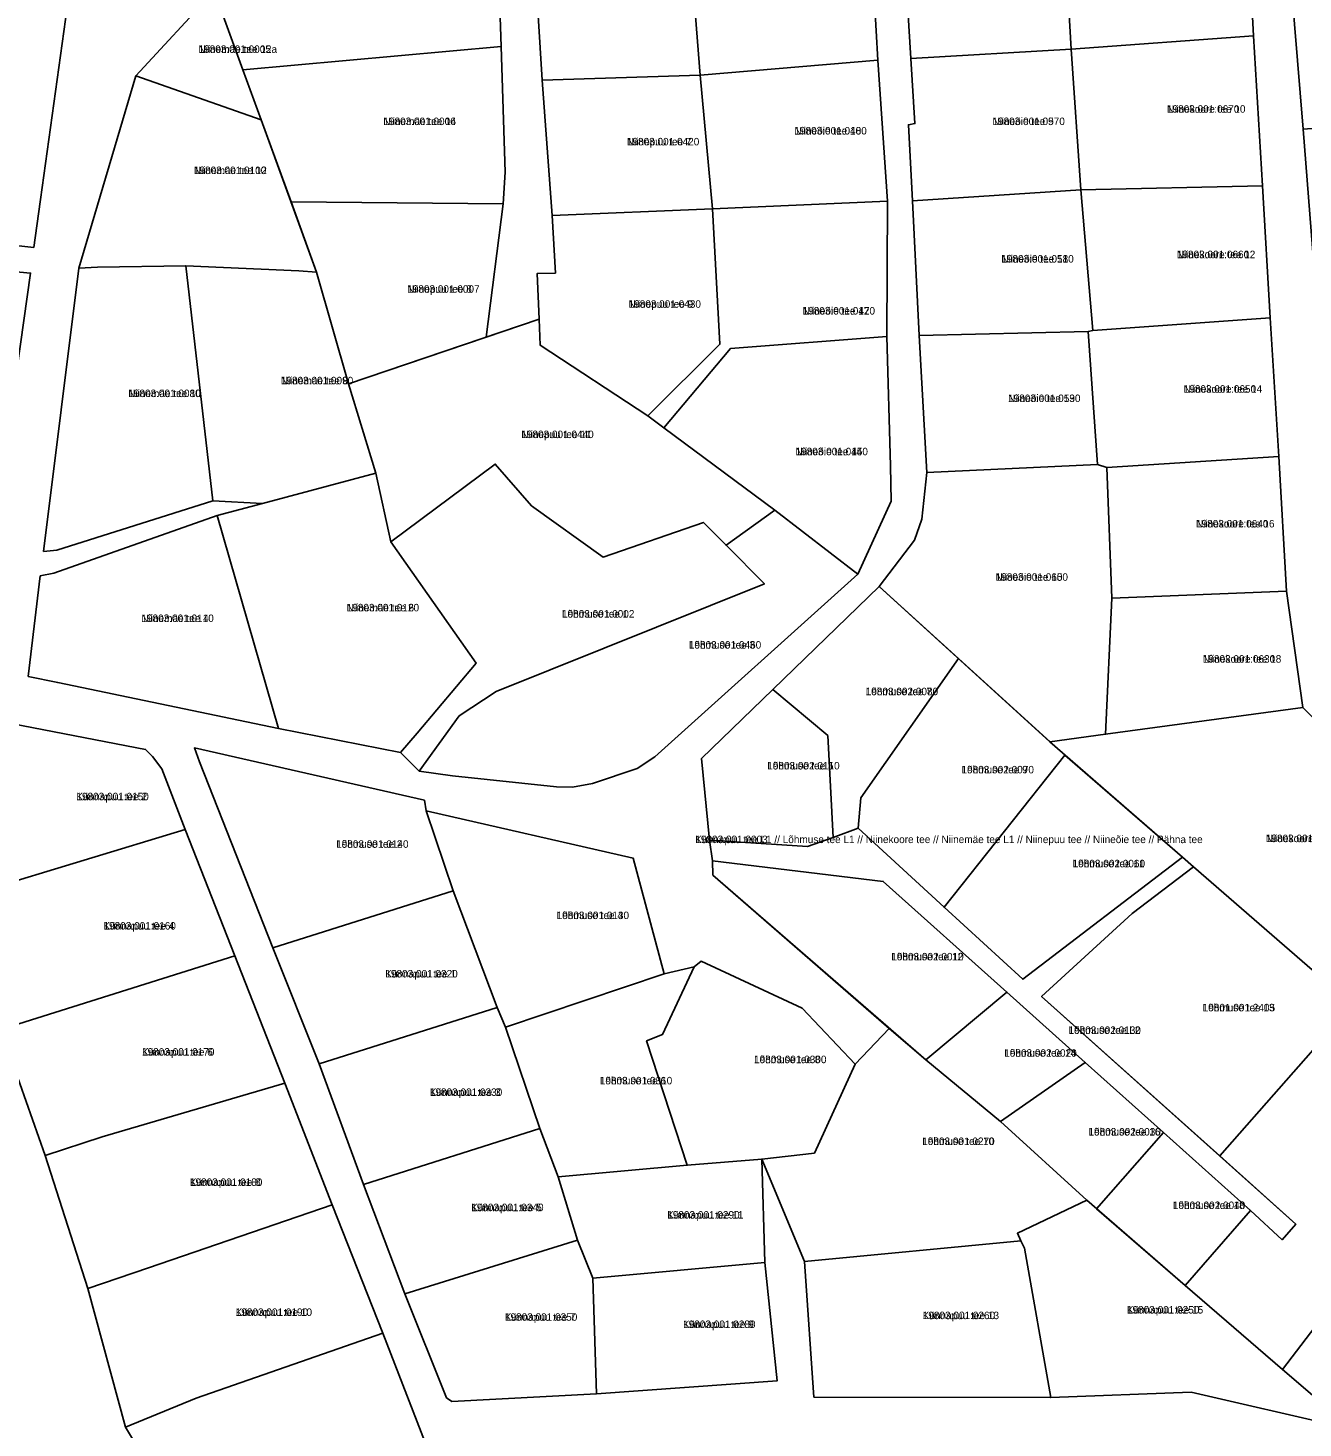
# Model space of a CAD drawing. Extents: x 516875 to 535633, y 6574491 to 6593094.
# Drawn here: x 521689.3 to 521944.6, y 6591928 to 6592208.3 of the extents above; entities that cross this region are included whole.
import ezdxf

# ---------------------------------------------------------------- set-up
doc = ezdxf.new("R2010")
doc.units = 0
for name, color, linetype in [('L_AADRESS', 7, 'Continuous'), ('PIIR', 7, 'Continuous'), ('TUNNUS', 7, 'Continuous')]:
    doc.layers.add(name, color=color, linetype=linetype)

msp = doc.modelspace()

# ---------------------------------------------------------------- linework, layer by layer
at = {"layer": 'PIIR'}
for points in [[(521940.61, 6592236.6), (521942.91, 6592237.96), (521975.67, 6592236.53), (521975.53, 6592224.7), (521977.35, 6592190.49), (521944.62, 6592187.97)], [(521866.04, 6592202.15), (521864.22, 6592232.76), (521866.15, 6592233.77), (521896.35, 6592235.26), (521898.2, 6592203.99)], [(521896.35, 6592235.26), (521931.96, 6592237.36), (521933.17, 6592237.01), (521934.78, 6592232.86), (521933.37, 6592230.79), (521934.69, 6592206.69), (521898.2, 6592203.99)], [(521821.3, 6592231.76), (521854.33, 6592233.21), (521857.76, 6592231.23), (521859.45, 6592201.8), (521823.92, 6592198.81)], [(521726.6, 6592215.69), (521747.49, 6592217.82), (521747.49, 6592223.01), (521780.82, 6592229.71), (521783.32, 6592226.15), (521784.02, 6592204.57), (521732.36, 6592199.91)], [(521792.29, 6592197.79), (521790.25, 6592230.25), (521821.3, 6592231.76), (521823.92, 6592198.81)], [(521656.25, 6592216.57), (521689.09, 6592218.47), (521694.09, 6592214.92), (521697.14, 6592212.36), (521690.48, 6592164.34), (521673.6, 6592166.16), (521668.99, 6592168.86), (521653.45, 6592196.6), (521652.38, 6592216.11)], [(521726.6, 6592215.69), (521732.36, 6592199.91), (521736.02, 6592189.86), (521710.89, 6592198.65)], [(521732.36, 6592199.91), (521784.02, 6592204.57), (521784.82, 6592179.41), (521784.43, 6592173.07), (521741.99, 6592173.48), (521736.02, 6592189.86)], [(521866.43, 6592173.64), (521865.57, 6592188.87), (521866.87, 6592189.13), (521866.04, 6592202.15), (521898.2, 6592203.99), (521900.11, 6592175.88)], [(521898.2, 6592203.99), (521934.69, 6592206.69), (521936.49, 6592176.65), (521900.11, 6592175.88)], [(521823.92, 6592198.81), (521859.45, 6592201.8), (521861.43, 6592173.58), (521826.35, 6592172.06)], [(521703.22, 6592160.38), (521699.53, 6592160.2), (521710.89, 6592198.65), (521736.02, 6592189.86), (521747.11, 6592159.38), (521743.56, 6592159.61), (521720.9, 6592160.66)], [(521794.26, 6592170.69), (521792.29, 6592197.79), (521823.92, 6592198.81), (521826.35, 6592172.06)], [(521936.49, 6592176.65), (521938.04, 6592150.21), (521902.51, 6592147.69), (521900.11, 6592175.88)], [(521741.99, 6592173.48), (521784.43, 6592173.07), (521781.06, 6592146.37), (521753.48, 6592137.02), (521747.11, 6592159.38)], [(521816.6, 6592128.17), (521813.39, 6592130.61), (521827.85, 6592144.94), (521826.35, 6592172.06), (521861.43, 6592173.58), (521861.25, 6592146.5), (521829.94, 6592144.06)], [(521902.51, 6592147.69), (521901.57, 6592147.48), (521867.71, 6592146.69), (521866.43, 6592173.64), (521900.11, 6592175.88)], [(521813.39, 6592130.61), (521791.89, 6592144.75), (521791.65, 6592149.96), (521791.25, 6592159.09), (521794.91, 6592159.19), (521794.26, 6592170.69), (521826.35, 6592172.06), (521827.85, 6592144.94)], [(521672.05, 6592158.02), (521673.1, 6592161.92), (521678.47, 6592160.23), (521689.85, 6592159.2), (521685.1, 6592125.56), (521659.5, 6592116.72), (521657.72, 6592121.29), (521647.38, 6592146.56)], [(521703.22, 6592160.38), (521720.9, 6592160.66), (521726.31, 6592113.6), (521695.07, 6592103.72), (521692.46, 6592103.46), (521699.53, 6592160.2)], [(521743.56, 6592159.61), (521747.11, 6592159.38), (521753.48, 6592137.02), (521758.95, 6592119.16), (521736.29, 6592113.08), (521726.31, 6592113.6), (521720.9, 6592160.66)], [(521816.6, 6592128.17), (521838.83, 6592111.75), (521829.09, 6592104.69), (521824.53, 6592109.28), (521804.44, 6592102.33), (521790.11, 6592112.61), (521782.88, 6592120.96), (521761.99, 6592105.36), (521758.95, 6592119.16), (521753.48, 6592137.02), (521791.65, 6592149.96), (521791.89, 6592144.75), (521813.39, 6592130.61)], [(521938.04, 6592150.21), (521939.71, 6592122.44), (521905.29, 6592120.27), (521903.47, 6592120.89), (521901.57, 6592147.48), (521902.51, 6592147.69)], [(521829.94, 6592144.06), (521861.25, 6592146.5), (521862.03, 6592120.62), (521862.14, 6592113.49), (521855.45, 6592098.92), (521838.83, 6592111.75), (521816.6, 6592128.17)], [(521869.3, 6592119.26), (521867.71, 6592146.69), (521901.57, 6592147.48), (521903.47, 6592120.89)], [(521761.99, 6592105.36), (521782.88, 6592120.96), (521790.11, 6592112.61), (521804.44, 6592102.33), (521824.53, 6592109.28), (521829.09, 6592104.69), (521836.74, 6592096.99), (521783.02, 6592075.42), (521775.64, 6592070.53), (521767.64, 6592059.46), (521763.9, 6592063.19), (521767.25, 6592067.07), (521779.02, 6592081.06)], [(521905.29, 6592120.27), (521906.34, 6592094.08), (521905.05, 6592066.86), (521893.89, 6592065.37), (521859.72, 6592096.42), (521866.82, 6592105.69), (521868.27, 6592109.93), (521869.3, 6592119.26), (521903.47, 6592120.89)], [(521905.29, 6592120.27), (521939.71, 6592122.44), (521941.31, 6592095.51), (521906.34, 6592094.08)], [(521736.29, 6592113.08), (521758.95, 6592119.16), (521761.99, 6592105.36), (521779.02, 6592081.06), (521767.25, 6592067.07), (521763.9, 6592063.19), (521739.5, 6592068.02), (521727.21, 6592110.65)], [(521775.64, 6592070.53), (521783.02, 6592075.42), (521836.74, 6592096.99), (521829.09, 6592104.69), (521838.83, 6592111.75), (521855.45, 6592098.92), (521814.8, 6592062.36), (521811.26, 6592059.99), (521802.31, 6592056.97), (521798.32, 6592056.25), (521795.11, 6592056.31), (521774.3, 6592058.53), (521767.64, 6592059.46)], [(521694.48, 6592099.11), (521727.21, 6592110.65), (521739.5, 6592068.02), (521695.28, 6592077.2), (521689.37, 6592078.43), (521691.79, 6592098.56)], [(521859.72, 6592096.42), (521875.6, 6592081.99), (521856.03, 6592054.12), (521855.54, 6592048.08), (521850.49, 6592046.18), (521849.47, 6592066.6), (521838.45, 6592075.83)], [(521906.34, 6592094.08), (521941.31, 6592095.51), (521944.54, 6592072.18), (521905.05, 6592066.86)], [(521875.6, 6592081.99), (521896.88, 6592062.65), (521872.73, 6592032.22), (521855.54, 6592048.08), (521856.03, 6592054.12)], [(521849.47, 6592066.6), (521850.49, 6592046.18), (521845.41, 6592044.35), (521825.78, 6592045.66), (521824.14, 6592062), (521838.45, 6592075.83)], [(521678.44, 6592044.05), (521681.99, 6592047.8), (521671.75, 6592071.76), (521712.85, 6592063.82), (521714.26, 6592062.42), (521716.13, 6592059.96), (521720.76, 6592047.76), (521680.27, 6592035.51)], [(521905.05, 6592066.86), (521944.54, 6592072.18), (521949.8, 6592066.84), (521956.14, 6592049.35), (521957.62, 6592043.92), (521957.58, 6592033.05), (521958.82, 6592029.22), (521947.95, 6592018.33), (521922.65, 6592040.34), (521920.48, 6592042.23), (521893.89, 6592065.37)], [(521723.65, 6592061.35), (521722.63, 6592064.11), (521768.68, 6592053.65), (521769.06, 6592051.5), (521774.45, 6592035.49), (521738.37, 6592024.12)], [(521896.88, 6592062.65), (521920.48, 6592042.23), (521888.46, 6592017.79), (521872.73, 6592032.22)], [(521783.26, 6592012.18), (521774.45, 6592035.49), (521769.06, 6592051.5), (521810.5, 6592042.04), (521816.66, 6592018.86), (521784.91, 6592008.2)], [(521680.19, 6592018.27), (521680.21, 6592022.8), (521680.27, 6592035.51), (521720.76, 6592047.76), (521730.7, 6592022.5), (521683.89, 6592007.74)], [(521845.41, 6592044.35), (521850.49, 6592046.18), (521855.54, 6592048.08), (521872.73, 6592032.22), (521888.46, 6592017.79), (521920.48, 6592042.23), (521922.65, 6592040.34), (521910.39, 6592030.94), (521892.26, 6592014.38), (521943.12, 6591968.75), (521940.4, 6591965.65), (521934.07, 6591971.5), (521916.66, 6591987.12), (521900.98, 6592001.16), (521885.29, 6592015.24), (521860.55, 6592037.38), (521826.37, 6592041.52), (521825.78, 6592045.66)], [(521860.55, 6592037.38), (521885.29, 6592015.24), (521869.05, 6592001.64), (521826.42, 6592038.67), (521826.37, 6592041.52)], [(521954.46, 6592012.61), (521927.9, 6591982.42), (521892.26, 6592014.38), (521910.39, 6592030.94), (521922.65, 6592040.34), (521947.95, 6592018.33)], [(521738.37, 6592024.12), (521774.45, 6592035.49), (521783.26, 6592012.18), (521747.6, 6592000.84)], [(521639.58, 6592001.15), (521639.64, 6592001.17), (521680.21, 6592022.8), (521680.19, 6592018.27), (521683.89, 6592007.74), (521692.77, 6591982.51), (521701.33, 6591955.9), (521708.82, 6591928.16), (521722.97, 6591904.65), (521731.68, 6591881.94), (521745.45, 6591847.74), (521757.09, 6591827.34), (521755.99, 6591825.24), (521698.88, 6591854.65), (521689.15, 6591863.66), (521680.26, 6591879.32), (521637.95, 6592000.51)], [(521692.77, 6591982.51), (521683.89, 6592007.74), (521730.7, 6592022.5), (521740.74, 6591996.97), (521704.14, 6591986.25)], [(521791.8, 6591987.92), (521784.91, 6592008.2), (521816.66, 6592018.86), (521822.69, 6592020.29), (521816.37, 6592006.72), (521813.18, 6592005.47), (521821.32, 6591980.57), (521795.44, 6591978.22)], [(521813.18, 6592005.47), (521816.37, 6592006.72), (521822.69, 6592020.29), (521824.09, 6592021.43), (521844.31, 6592012.02), (521854.94, 6592000.77), (521846.76, 6591983.01), (521836.21, 6591981.79), (521821.32, 6591980.57)], [(521885.29, 6592015.24), (521900.98, 6592001.16), (521884.04, 6591989.34), (521869.05, 6592001.64)], [(521747.6, 6592000.84), (521783.26, 6592012.18), (521784.91, 6592008.2), (521791.8, 6591987.92), (521756.51, 6591976.72)], [(521943.12, 6591968.75), (521927.9, 6591982.42), (521954.46, 6592012.61), (521968.51, 6592000.46), (521969.89, 6591999.23), (521979.93, 6591990.62), (521961.47, 6591970.68), (521962, 6591967.92), (521940.5, 6591939.68), (521921.02, 6591956.48), (521934.07, 6591971.5), (521940.4, 6591965.65)], [(521836.21, 6591981.79), (521846.76, 6591983.01), (521854.94, 6592000.77), (521861.76, 6592007.97), (521869.05, 6592001.64), (521884.04, 6591989.34), (521901.29, 6591973.58), (521887.4, 6591966.94), (521888.12, 6591965.45), (521844.75, 6591961.27)], [(521900.98, 6592001.16), (521916.66, 6591987.12), (521903.27, 6591971.85), (521901.29, 6591973.58), (521884.04, 6591989.34)], [(521701.33, 6591955.9), (521692.77, 6591982.51), (521704.14, 6591986.25), (521740.74, 6591996.97), (521750.24, 6591972.63), (521713.44, 6591960.04)], [(521995.95, 6591976.56), (521974.79, 6591952.48), (521993.36, 6591924.57), (521990, 6591920.93), (521974.68, 6591932.42), (521954.24, 6591933.23), (521947.41, 6591933.73), (521940.5, 6591939.68), (521962, 6591967.92), (521961.47, 6591970.68), (521979.93, 6591990.62)], [(521756.51, 6591976.72), (521791.8, 6591987.92), (521795.44, 6591978.22), (521799.34, 6591965.59), (521764.77, 6591954.82)], [(521916.66, 6591987.12), (521934.07, 6591971.5), (521921.02, 6591956.48), (521903.27, 6591971.85)], [(521799.34, 6591965.59), (521795.44, 6591978.22), (521821.32, 6591980.57), (521836.21, 6591981.79), (521836.83, 6591961.12), (521802.39, 6591957.97)], [(521708.82, 6591928.16), (521701.33, 6591955.9), (521713.44, 6591960.04), (521750.24, 6591972.63), (521760.37, 6591946.92), (521723.01, 6591933.96)], [(521887.4, 6591966.94), (521901.29, 6591973.58), (521921.02, 6591956.48), (521940.5, 6591939.68), (521947.41, 6591933.73), (521954.24, 6591933.23), (521952.28, 6591928.18), (521922.16, 6591935.12), (521894.09, 6591934.06), (521888.85, 6591963.96), (521888.12, 6591965.45)], [(521773.11, 6591934.02), (521764.77, 6591954.82), (521799.34, 6591965.59), (521802.39, 6591957.97), (521803.16, 6591934.83), (521774.2, 6591933.27)], [(521844.82, 6591960.28), (521844.75, 6591961.27), (521888.12, 6591965.45), (521888.85, 6591963.96), (521894.09, 6591934.06), (521846.65, 6591934.15)], [(521802.39, 6591957.97), (521836.83, 6591961.12), (521839.32, 6591937.41), (521803.16, 6591934.83)], [(521722.97, 6591904.65), (521708.82, 6591928.16), (521723.01, 6591933.96), (521760.37, 6591946.92), (521770.46, 6591920.93), (521731.65, 6591909.09)]]:
    msp.add_lwpolyline(points, close=True, dxfattribs=at)
for points in [[(521940.61, 6592236.6), (521944.62, 6592187.97), (521946.72, 6592160.75), (521947.99, 6592133.85), (521949.86, 6592106.6), (521951.66, 6592079.69), (521954.85, 6592065.61), (521961.38, 6592049.9), (521956.14, 6592049.35), (521949.8, 6592066.84), (521944.54, 6592072.18), (521941.31, 6592095.51), (521939.71, 6592122.44), (521938.04, 6592150.21), (521936.49, 6592176.65), (521934.69, 6592206.69), (521933.37, 6592230.79)], [(521864.22, 6592232.76), (521866.04, 6592202.15), (521866.87, 6592189.13), (521865.57, 6592188.87), (521866.43, 6592173.64), (521867.71, 6592146.69), (521869.3, 6592119.26), (521868.27, 6592109.93), (521866.82, 6592105.69), (521859.72, 6592096.42), (521838.45, 6592075.83), (521824.14, 6592062), (521825.78, 6592045.66), (521826.37, 6592041.52), (521826.42, 6592038.67), (521861.76, 6592007.97), (521854.94, 6592000.77), (521844.31, 6592012.02), (521824.09, 6592021.43), (521822.69, 6592020.29), (521816.66, 6592018.86), (521810.5, 6592042.04), (521769.06, 6592051.5), (521768.68, 6592053.65), (521722.63, 6592064.11), (521723.65, 6592061.35), (521738.37, 6592024.12), (521747.6, 6592000.84), (521756.51, 6591976.72), (521764.77, 6591954.82), (521773.11, 6591934.02), (521774.2, 6591933.27), (521803.16, 6591934.83), (521839.32, 6591937.41), (521836.83, 6591961.12), (521836.21, 6591981.79), (521844.75, 6591961.27), (521844.82, 6591960.28), (521846.65, 6591934.15), (521894.09, 6591934.06), (521922.16, 6591935.12), (521952.28, 6591928.18)], [(521726.6, 6592215.69), (521710.89, 6592198.65), (521699.53, 6592160.2), (521692.46, 6592103.46), (521695.07, 6592103.72), (521726.31, 6592113.6), (521736.29, 6592113.08), (521727.21, 6592110.65), (521694.48, 6592099.11), (521691.79, 6592098.56), (521689.37, 6592078.43), (521695.28, 6592077.2), (521739.5, 6592068.02), (521763.9, 6592063.19), (521767.64, 6592059.46), (521774.3, 6592058.53), (521795.11, 6592056.31), (521798.32, 6592056.25), (521802.31, 6592056.97), (521811.26, 6592059.99), (521814.8, 6592062.36), (521855.45, 6592098.92), (521862.14, 6592113.49), (521862.03, 6592120.62), (521861.25, 6592146.5), (521861.43, 6592173.58), (521859.45, 6592201.8), (521857.76, 6592231.23)], [(521790.25, 6592230.25), (521792.29, 6592197.79), (521794.26, 6592170.69), (521794.91, 6592159.19), (521791.25, 6592159.09), (521791.65, 6592149.96), (521781.06, 6592146.37), (521784.43, 6592173.07), (521784.82, 6592179.41), (521784.02, 6592204.57), (521783.32, 6592226.15)], [(521673.6, 6592166.16), (521690.48, 6592164.34), (521697.14, 6592212.36)], [(521685.1, 6592125.56), (521689.85, 6592159.2), (521678.47, 6592160.23)], [(521770.46, 6591920.93), (521760.37, 6591946.92), (521750.24, 6591972.63), (521740.74, 6591996.97), (521730.7, 6592022.5), (521720.76, 6592047.76), (521716.13, 6592059.96), (521714.26, 6592062.42), (521712.85, 6592063.82), (521671.75, 6592071.76)]]:
    msp.add_lwpolyline(points, dxfattribs=at)

# ---------------------------------------------------------------- texts
at = {"layer": 'L_AADRESS'}
for s, p in [('Niinemäe tee 12a', (521723.46, 6592203.27)), ('Niinekoore tee 10', (521917.34, 6592191.29)), ('Niinemäe tee 14', (521760.46, 6592188.82)), ('Niineõie tee 9', (521882.4, 6592188.82)), ('Niineõie tee 10', (521842.75, 6592186.93)), ('Niinepuu tee 7', (521809.22, 6592184.75)), ('Niinemäe tee 12', (521722.53, 6592179.01)), ('Niineõie tee 11', (521884.18, 6592161.29)), ('Niinekoore tee 12', (521919.31, 6592162.17)), ('Niinepuu tee 8', (521765.23, 6592155.25)), ('Niinepuu tee 9', (521809.55, 6592152.24)), ('Niineõie tee 12', (521844.4, 6592150.88)), ('Niinemäe tee 8', (521739.93, 6592136.92)), ('Niinekoore tee 14', (521920.69, 6592135.24)), ('Niinemäe tee 10', (521709.39, 6592134.36)), ('Niineõie tee 13', (521885.53, 6592133.37)), ('Niinepuu tee 11', (521788.08, 6592126.15)), ('Niineõie tee 14', (521842.98, 6592122.71)), ('Niinekoore tee 16', (521923.16, 6592108.26)), ('Niineõie tee 15', (521883.03, 6592097.58)), ('Niinemäe tee 6', (521753.12, 6592091.46)), ('Niinemäe tee 4', (521712.02, 6592089.33)), ('Lõhmuse tee 1', (521796.23, 6592090.21)), ('Lõhmuse tee 3', (521821.62, 6592084)), ('Niinekoore tee 18', (521924.51, 6592081.19)), ('Lõhmuse tee 7', (521857.03, 6592074.67)), ('Lõhmuse tee 5', (521837.32, 6592059.81)), ('Lõhmuse tee 9', (521876.21, 6592059.02)), ('Künnapuu tee 2', (521699.01, 6592053.64)), ('Lõhmuse tee 2', (521751.01, 6592044.12)), ('Künnapuu tee L1 // Lõhmuse tee L1 // Niinekoore tee // Niinemäe tee L1 // Niinepuu tee // Niineõie tee // Pähna tee', (521822.91, 6592045.06)), ('Niinekoore tee 20', (521937.13, 6592045.25)), ('Lõhmuse tee 11', (521898.46, 6592040.22)), ('Lõhmuse tee 4', (521795.16, 6592029.85)), ('Künnapuu tee 4', (521704.43, 6592027.75)), ('Lõhmuse tee 12', (521862.15, 6592021.58)), ('Künnapuu tee 1', (521760.86, 6592018.16)), ('Lõhmuse tee 13', (521924.49, 6592011.38)), ('Lõhmuse tee L2', (521897.63, 6592006.86)), ('Künnapuu tee 6', (521712.15, 6592002.51)), ('Lõhmuse tee 8', (521834.68, 6592001)), ('Lõhmuse tee 14', (521884.77, 6592002.29)), ('Lõhmuse tee 6', (521803.8, 6591996.76)), ('Künnapuu tee 3', (521769.77, 6591994.45)), ('Lõhmuse tee 10', (521868.35, 6591984.62)), ('Lõhmuse tee 16', (521901.63, 6591986.51)), ('Künnapuu tee 8', (521721.74, 6591976.43)), ('Künnapuu tee 5', (521778.04, 6591971.37)), ('Künnapuu tee 11', (521817.29, 6591969.88)), ('Lõhmuse tee 18', (521918.53, 6591971.8)), ('Künnapuu tee 10', (521730.91, 6591950.4)), ('Künnapuu tee 15', (521909.33, 6591950.88)), ('Künnapuu tee 7', (521784.8, 6591949.43)), ('Künnapuu tee 9', (521820.47, 6591947.98)), ('Künnapuu tee 13', (521868.45, 6591949.75))]:
    msp.add_text(s, height=1.5, dxfattribs=at).set_placement(p)
at = {"layer": 'TUNNUS'}
for s, p in [('19803:001:0005', (521723.46, 6592203.27)), ('19803:001:0670', (521917.34, 6592191.29)), ('19803:001:0006', (521760.46, 6592188.82)), ('19803:001:0570', (521882.4, 6592188.82)), ('19803:001:0480', (521842.75, 6592186.93)), ('19803:001:0420', (521809.22, 6592184.75)), ('19803:001:0100', (521722.53, 6592179.01)), ('19803:001:0580', (521884.18, 6592161.29)), ('19803:001:0660', (521919.31, 6592162.17)), ('19803:001:0007', (521765.23, 6592155.25)), ('19803:001:0430', (521809.55, 6592152.24)), ('19803:001:0470', (521844.4, 6592150.88)), ('19803:001:0090', (521739.93, 6592136.92)), ('19803:001:0650', (521920.69, 6592135.24)), ('19803:001:0080', (521709.39, 6592134.36)), ('19803:001:0590', (521885.53, 6592133.37)), ('19803:001:0440', (521788.08, 6592126.15)), ('19803:001:0450', (521842.98, 6592122.71)), ('19803:001:0640', (521923.16, 6592108.26)), ('19803:001:0600', (521883.03, 6592097.58)), ('19803:001:0120', (521753.12, 6592091.46)), ('19803:001:0110', (521712.02, 6592089.33)), ('19803:001:0002', (521796.23, 6592090.21)), ('19803:001:0460', (521821.62, 6592084)), ('19803:001:0630', (521924.51, 6592081.19)), ('19803:002:0080', (521857.03, 6592074.67)), ('19803:002:0110', (521837.32, 6592059.81)), ('19803:002:0070', (521876.21, 6592059.02)), ('19803:001:0150', (521699.01, 6592053.64)), ('19803:001:0140', (521751.01, 6592044.12)), ('19803:001:0003', (521822.91, 6592045.06)), ('19803:001:0620', (521937.13, 6592045.25)), ('19803:002:0060', (521898.46, 6592040.22)), ('19803:001:0130', (521795.16, 6592029.85)), ('19803:001:0160', (521704.43, 6592027.75)), ('19803:002:0010', (521862.15, 6592021.58)), ('19803:001:0320', (521760.86, 6592018.16)), ('19801:001:2405', (521924.49, 6592011.38)), ('19803:002:0130', (521897.63, 6592006.86)), ('19803:001:0170', (521712.15, 6592002.51)), ('19803:001:0300', (521834.68, 6592001)), ('19803:002:0020', (521884.77, 6592002.29)), ('19803:001:0310', (521803.8, 6591996.76)), ('19803:001:0330', (521769.77, 6591994.45)), ('19803:001:0270', (521868.35, 6591984.62)), ('19803:002:0030', (521901.63, 6591986.51)), ('19803:001:0180', (521721.74, 6591976.43)), ('19803:001:0340', (521778.04, 6591971.37)), ('19803:001:0290', (521817.29, 6591969.88)), ('19803:002:0040', (521918.53, 6591971.8)), ('19803:001:0190', (521730.91, 6591950.4)), ('19803:001:0250', (521909.33, 6591950.88)), ('19803:001:0350', (521784.8, 6591949.43)), ('19803:001:0280', (521820.47, 6591947.98)), ('19803:001:0260', (521868.45, 6591949.75))]:
    msp.add_text(s, height=1.5, dxfattribs=at).set_placement(p)

doc.saveas('drawing.dxf')
